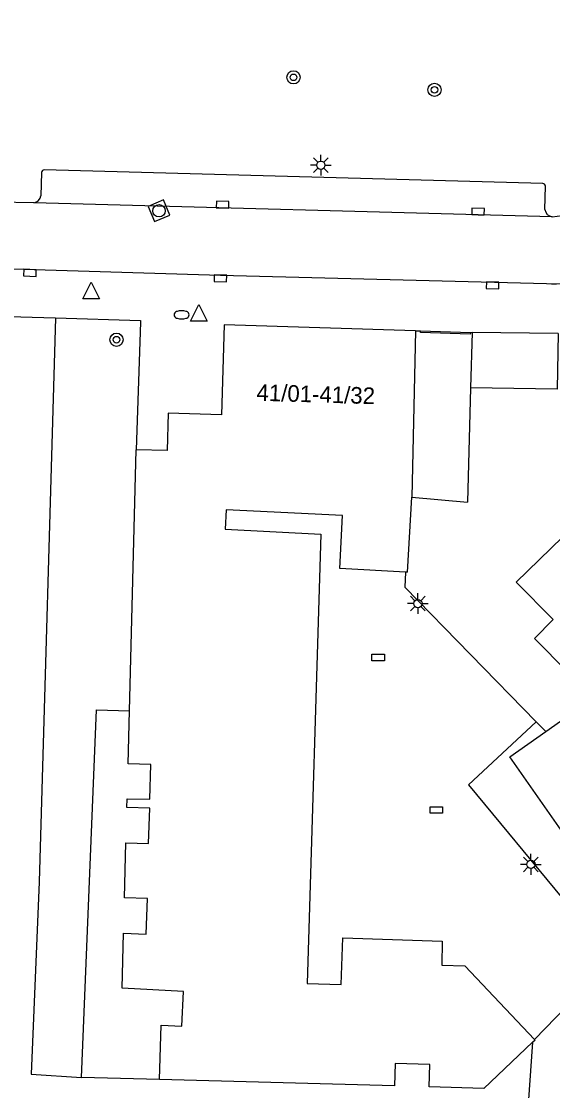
# Model space of a CAD drawing. Extents: x 132573 to 132944, y 398226 to 398676.
# Drawn here: x 132790.1 to 132822.1, y 398438.1 to 398502.5 of the extents above; entities that cross this region are included whole.
import ezdxf

# ---------------------------------------------------------------- set-up
doc = ezdxf.new("R2010")
doc.units = 0
for name, color, linetype in [('gg-afsc-erfafscheiding', 7, 'Continuous'), ('gg-afsc-muur', 7, 'Continuous'), ('gg-anno-huisnummerreeks BGT', 7, 'Continuous'), ('gg-bbg-gedigitaliseerde bebouwing', 7, 'Continuous'), ('gg-bbg-gedigitaliseerde bijgebouw', 7, 'Continuous'), ('gg-bbg-hoofdgebouw', 7, 'Continuous'), ('gg-bbg-luifel en loopbrug', 7, 'Continuous'), ('gg-bbg-tussenscheiding', 7, 'Continuous'), ('gg-knt-verharding', 7, 'Continuous'), ('gg-knt-verharding nz', 7, 'Continuous'), ('gt-grn-groengrens', 7, 'Continuous'), ('gt-symb-boom', 7, 'Continuous'), ('gt-symb-brandkraan', 7, 'Continuous'), ('gt-symb-kolk', 7, 'Continuous'), ('gt-symb-kolk center center', 7, 'Continuous'), ('gt-symb-lichtmast', 7, 'Continuous'), ('gt-symb-rioolschacht', 7, 'Continuous'), ('gt-symb-waterafsluiter', 7, 'Continuous')]:
    doc.layers.add(name, color=color, linetype=linetype)

msp = doc.modelspace()

# ---------------------------------------------------------------- linework, layer by layer
at = {"layer": 'gg-afsc-erfafscheiding'}
msp.add_line((132798.45, 398438.73), (132793.754, 398438.858), dxfattribs=at)
msp.add_lwpolyline([(132793.754, 398438.858), (132794.656, 398461.003), (132796.633, 398460.952)], dxfattribs=at)
at = {"layer": 'gg-afsc-muur'}
msp.add_line((132821.14, 398460.29), (132821.712, 398459.704), dxfattribs=at)
msp.add_lwpolyline([(132813.265, 398469.296), (132813.22, 398468.4), (132821.14, 398460.29)], dxfattribs=at)
at = {"layer": 'gg-bbg-gedigitaliseerde bebouwing'}
for p, q in [((132813.38, 398469.29), (132813.643, 398473.822)), ((132813.643, 398473.822), (132816.999, 398473.523))]:
    msp.add_line(p, q, dxfattribs=at)
for points in [[(132822.151, 398466.45), (132819.925, 398468.698), (132826.95, 398475.5)], [(132821.712, 398459.704), (132824.986, 398462.002), (132828.142, 398457.511)]]:
    msp.add_lwpolyline(points, dxfattribs=at)
at = {"layer": 'gg-bbg-gedigitaliseerde bijgebouw'}
msp.add_lwpolyline([(132822.151, 398466.45), (132821.034, 398465.295), (132823.036, 398463.274), (132824.153, 398464.429)], dxfattribs=at)
at = {"layer": 'gg-bbg-hoofdgebouw'}
for p, q in [((132813.864, 398483.843), (132814.174, 398483.834)), ((132817.172, 398483.743), (132817.28, 398483.74)), ((132817.28, 398483.74), (132817.188, 398480.392)), ((132817.188, 398480.392), (132816.999, 398473.523)), ((132796.633, 398460.952), (132797.04, 398476.67)), ((132813.38, 398469.29), (132813.265, 398469.296))]:
    msp.add_line(p, q, dxfattribs=at)
for points in [[(132813.864, 398483.843), (132802.34, 398484.19), (132802.17, 398478.78), (132798.97, 398478.87), (132798.9, 398476.62), (132797.04, 398476.67)], [(132817.172, 398483.743), (132817.169, 398483.633), (132814.17, 398483.724), (132814.174, 398483.834)], [(132813.265, 398469.296), (132809.3, 398469.52), (132809.46, 398472.7), (132802.47, 398473.05), (132802.41, 398471.88), (132808.16, 398471.59), (132807.34, 398444.52), (132809.39, 398444.45), (132809.49, 398447.26), (132815.48, 398447.06), (132815.46, 398445.62), (132816.84, 398445.58), (132821.039, 398441.152)], [(132798.45, 398438.73), (132798.548, 398442.003), (132799.78, 398441.94), (132799.89, 398444.03), (132796.19, 398444.24), (132796.27, 398447.54), (132797.65, 398447.49), (132797.72, 398449.63), (132796.34, 398449.67), (132796.42, 398453), (132797.79, 398452.96), (132797.86, 398455.08), (132796.48, 398455.12), (132796.49, 398455.65), (132797.86, 398455.62), (132797.92, 398457.72), (132796.55, 398457.76), (132796.633, 398460.952)], [(132830.14, 398454.22), (132824.9, 398450.55), (132819.54, 398458.18), (132821.712, 398459.704)], [(132820.924, 398440.982), (132817.98, 398438.19), (132814.7, 398438.29), (132814.74, 398439.64), (132812.65, 398439.7), (132812.61, 398438.35), (132798.45, 398438.73)], [(132820.924, 398440.982), (132821.07, 398441.12), (132821.039, 398441.152)]]:
    msp.add_lwpolyline(points, dxfattribs=at)
at = {"layer": 'gg-bbg-luifel en loopbrug'}
msp.add_line((132822.457, 398483.665), (132817.28, 398483.74), dxfattribs=at)
msp.add_lwpolyline([(132822.457, 398483.665), (132822.408, 398480.315), (132817.188, 398480.392)], dxfattribs=at)
at = {"layer": 'gg-bbg-tussenscheiding'}
msp.add_line((132813.864, 398483.843), (132813.643, 398473.822), dxfattribs=at)
at = {"layer": 'gg-knt-verharding'}
for p, q in [((132791.342, 398493.369), (132791.291, 398491.973)), ((132821.528, 398492.714), (132791.503, 398493.531)), ((132821.653, 398491.134), (132821.698, 398492.545)), ((132790.873, 398491.552), (132788.365, 398491.599)), ((132784.242, 398484.833), (132792.187, 398484.61)), ((132797.29, 398484.354), (132797.04, 398476.67)), ((132814.174, 398483.834), (132817.172, 398483.743)), ((132821.039, 398441.152), (132825.68, 398445.95))]:
    msp.add_line(p, q, dxfattribs=at)
for points in [[(132788.239, 398487.608), (132802.116, 398487.197), (132821.762, 398486.687)], [(132792.187, 398484.61), (132797.293, 398484.466), (132797.29, 398484.354)], [(132821.14, 398460.29), (132817.06, 398456.49), (132822.75, 398449.61)], [(132820.924, 398440.982), (132819.807, 398425.182), (132819.656, 398423.517), (132803.51, 398424.16)]]:
    msp.add_lwpolyline(points, dxfattribs=at)
for centre, radius, start, end in [((132819.131, 398492.312), 31.346, 140.01365, 175.24514), ((132791.496, 398493.377), 0.154, 87.36949, 182.98528), ((132821.512, 398492.528), 0.187, 5.28084, 85.05718), ((132790.815, 398492.028), 0.479, 276.94511, 353.46464), ((132822.167, 398491.229), 0.523, 190.47462, 263.06023), ((132821.858, 398495.754), 5.05, 272.79508, 299.96492), ((132822.294, 398493.902), 7.235, 265.78178, 303.6979)]:
    msp.add_arc(centre, radius, start, end, dxfattribs=at)
at = {"layer": 'gg-knt-verharding nz'}
msp.add_line((132822.104, 398490.71), (132790.873, 398491.552), dxfattribs=at)
at = {"layer": 'gt-grn-groengrens'}
msp.add_lwpolyline([(132792.187, 398484.61), (132791.194, 398450.636), (132790.713, 398439.051), (132793.754, 398438.858)], dxfattribs=at)
at = {"layer": 'gt-symb-boom'}
for centre, radius in [((132806.515, 398499.105), 0.4), ((132806.515, 398499.105), 0.2), ((132815.014, 398498.353), 0.4), ((132815.014, 398498.353), 0.2), ((132795.855, 398483.3), 0.4), ((132795.855, 398483.3), 0.2)]:
    msp.add_circle(centre, radius, dxfattribs=at)
at = {"layer": 'gt-symb-brandkraan'}
for centre, radius, start, end in [((132799.532, 398484.797), 0.206, 108.0027, 252.86884), ((132800.395, 398482.14), 3, 107.32781, 108.0027), ((132799.781, 398484.108), 0.938, 73.54375, 107.32781), ((132799.197, 398482.13), 3, 72.86885, 73.54375), ((132800.02, 398484.801), 0.206, 288.00271, 72.86885), ((132800.355, 398487.468), 3, 252.86884, 253.54373), ((132799.771, 398485.49), 0.938, 253.54373, 287.32783), ((132799.157, 398487.458), 3, 287.32783, 288.00271)]:
    msp.add_arc(centre, radius, start, end, dxfattribs=at)
at = {"layer": 'gt-symb-kolk'}
for points in [[(132802.237, 398491.241), (132802.612, 398491.231), (132802.623, 398491.631), (132801.873, 398491.651), (132801.862, 398491.251), (132802.237, 398491.241)], [(132817.635, 398490.823), (132818.01, 398490.813), (132818.02, 398491.213), (132817.27, 398491.232), (132817.26, 398490.833), (132817.635, 398490.823)], [(132790.642, 398487.529), (132790.267, 398487.541), (132790.254, 398487.142), (132791.004, 398487.117), (132791.017, 398487.517), (132790.642, 398487.529)], [(132802.116, 398487.197), (132801.741, 398487.208), (132801.73, 398486.808), (132802.479, 398486.786), (132802.491, 398487.186), (132802.116, 398487.197)], [(132818.517, 398486.775), (132818.142, 398486.785), (132818.132, 398486.385), (132818.882, 398486.366), (132818.892, 398486.765), (132818.517, 398486.775)]]:
    msp.add_lwpolyline(points, dxfattribs=at)
at = {"layer": 'gt-symb-kolk center center'}
for points in [[(132811.24, 398464.354), (132811.99, 398464.354), (132811.99, 398463.954), (132811.24, 398463.954)], [(132814.752, 398455.169), (132815.502, 398455.169), (132815.502, 398454.769), (132814.752, 398454.769)]]:
    msp.add_lwpolyline(points, close=True, dxfattribs=at)
at = {"layer": 'gt-symb-lichtmast'}
for p, q in [((132808.164, 398494.059), (132808.164, 398494.434)), ((132807.914, 398493.809), (132807.539, 398493.809)), ((132807.987, 398493.986), (132807.722, 398494.251)), ((132808.341, 398493.986), (132808.606, 398494.251)), ((132808.414, 398493.809), (132808.789, 398493.809)), ((132807.987, 398493.632), (132807.722, 398493.367)), ((132808.164, 398493.559), (132808.164, 398493.184)), ((132808.606, 398493.367), (132808.341, 398493.632)), ((132814.011, 398467.652), (132814.011, 398468.027)), ((132813.761, 398467.402), (132813.386, 398467.402)), ((132813.834, 398467.579), (132813.569, 398467.844)), ((132814.188, 398467.579), (132814.453, 398467.844)), ((132814.261, 398467.402), (132814.636, 398467.402)), ((132813.834, 398467.225), (132813.569, 398466.96)), ((132814.011, 398467.152), (132814.011, 398466.777)), ((132814.453, 398466.96), (132814.188, 398467.225)), ((132820.644, 398451.873), (132820.379, 398452.138)), ((132820.821, 398451.946), (132820.821, 398452.321)), ((132820.998, 398451.873), (132821.263, 398452.138)), ((132820.571, 398451.696), (132820.196, 398451.696)), ((132820.644, 398451.519), (132820.379, 398451.254)), ((132820.821, 398451.446), (132820.821, 398451.071)), ((132821.263, 398451.254), (132820.998, 398451.519)), ((132821.071, 398451.696), (132821.446, 398451.696))]:
    msp.add_line(p, q, dxfattribs=at)
for centre in [(132808.164, 398493.809), (132814.011, 398467.402), (132820.821, 398451.696)]:
    msp.add_circle(centre, 0.25, dxfattribs=at)
at = {"layer": 'gt-symb-rioolschacht'}
msp.add_lwpolyline([(132799.07, 398490.801), (132798.681, 398491.722), (132797.76, 398491.333), (132798.149, 398490.412)], close=True, dxfattribs=at)
msp.add_circle((132798.415, 398491.067), 0.375, dxfattribs=at)
at = {"layer": 'gt-symb-waterafsluiter'}
for p, q in [((132793.831, 398485.756), (132794.331, 398486.756)), ((132794.331, 398486.756), (132794.831, 398485.756)), ((132794.831, 398485.756), (132793.831, 398485.756)), ((132800.313, 398484.415), (132800.813, 398485.415)), ((132800.813, 398485.415), (132801.313, 398484.415)), ((132801.313, 398484.415), (132800.313, 398484.415))]:
    msp.add_line(p, q, dxfattribs=at)

# ---------------------------------------------------------------- texts
at = {"layer": 'gg-anno-huisnummerreeks BGT'}
msp.add_text('41/01-41/32', height=1, rotation=358.3, dxfattribs=at).set_placement((132804.278, 398479.627))

doc.saveas('drawing.dxf')
